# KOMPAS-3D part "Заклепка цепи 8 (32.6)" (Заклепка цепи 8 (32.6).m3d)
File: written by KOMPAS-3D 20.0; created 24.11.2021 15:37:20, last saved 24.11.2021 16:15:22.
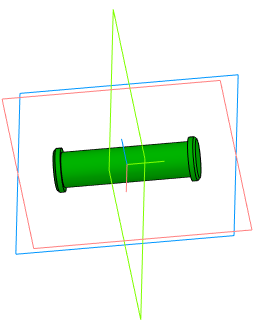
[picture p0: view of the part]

Document properties: Полное имя файла: C:\!WORK!\ЗИГ-18.240.00 Линия ЗигЗаг\Цепь\Заклепка цепи 8 (61.89) — копия.m3d

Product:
- Part/product: Заклепка цепи 8 (32.6)
    Материал: Сталь 45  ГОСТ 1050-2013 (density 7810 kg/m3)
    Масса: 0.0134894

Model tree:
1. Эскиз:1
2. Элемент вращения:1
     Угол 1 = 360
3. Фаска:1  (with: Элемент вращения:1)  (labels: Сталь 45  ГОСТ 1050-2013)
     Угол = 45; Длина 1 = 0.5; Длина 2 = 0.5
